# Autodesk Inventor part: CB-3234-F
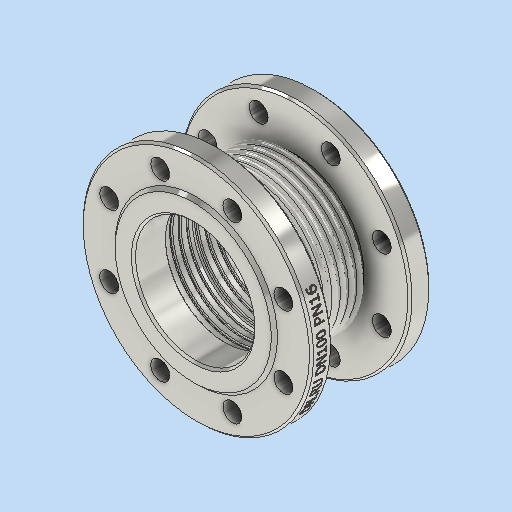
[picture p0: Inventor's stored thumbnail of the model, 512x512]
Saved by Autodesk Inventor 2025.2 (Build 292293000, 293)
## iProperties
Company: DN.RU
Created: 2026-04
Part Number: CB-3234-F
Material: Типовые
Document SubType Name: Modeling
Designer: DN.RU
Density: 6.48472 g/cm^3
Appearance: По умолчанию
Description: D140-02116
Mass: 8200 g
Surface Area: 3641.66 cm^2
Volume: 1264.51 cm^3
Author: DN.RU
Title: Компенсатор сильфонный осевой DN.ru Ду100 Ру16
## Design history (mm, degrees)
sketch "Эскиз1"
  geometry: L1 (0, 0)-(0, -60); L2 (63, -60)-(63, 0); L3 (63, 0)-(0, 0); L4 (63, 0)-(63, -4); L5 (55, -4)-(71, -4); L6 (55, -6.5)-(71, -6.5); L7 (71, -1.5)-(55, -1.5); L8 (71, -4.5)-(55, -4.5); L9 (55, -3.5)-(71, -3.5); L10 (71, -9.5)-(55, -9.5); L11 (55, -11.5)-(71, -11.5); L12 (55, -12)-(71, -12); L13 (55, -14.5)-(71, -14.5); L14 (71, -12.5)-(55, -12.5); L15 (71, -17.5)-(55, -17.5); L16 (55, -19.5)-(71, -19.5); L17 (55, -20)-(71, -20); L18 (55, -22.5)-(71, -22.5); L19 (71, -20.5)-(55, -20.5); L20 (71, -25.5)-(55, -25.5); L21 (55, -27.5)-(71, -27.5); L22 (55, -28)-(71, -28); L23 (55, -30.5)-(71, -30.5); L24 (71, -28.5)-(55, -28.5); L25 (0, -60)-(63, -60); L26 (63, -60)-(57, -60); L27 (63, -25.5)-(61, -25.5); L28 (57, -60)-(57, -28.5); L29 (63, -27.5)-(61, -27.5); L30 (61, -27.5)-(61, -20.5); L31 (63, -19.5)-(61, -19.5); L32 (61, -19.5)-(61, -12.5); L33 (63, -11.5)-(61, -11.5); L34 (61, -11.5)-(61, -4.5); L35 (63, -3.5)-(62, -3.5); L36 (62, -3.5)-(61, 0); L37 (0, -60)-(0, -37); L38 (0, -37)-(110, -37); L39 (110, -37)-(110, -60); L40 (110, -60)-(0, -60); L41 (63, -37)-(63, -47); L42 (63, -47)-(66, -47); L43 (66, -47)-(66, -37); L44 (66, -37)-(63, -37); A1 r 2.5 centre (55, -4) between (55, -1.5) and (55, -6.5); A2 r 2.5 centre (71, -4) between (71, -6.5) and (71, -1.5); A3 r 0.5 centre (55, -4) between (55, -3.5) and (55, -4.5); A4 r 0.5 centre (71, -4) between (71, -4.5) and (71, -3.5); A5 r 0.5 centre (55, -12) between (55, -11.5) and (55, -12.5); A6 r 2.5 centre (55, -12) between (55, -9.5) and (55, -14.5); A7 r 0.5 centre (71, -12) between (71, -12.5) and (71, -11.5); A8 r 2.5 centre (71, -12) between (71, -14.5) and (71, -9.5); A9 r 0.5 centre (55, -20) between (55, -19.5) and (55, -20.5); A10 r 2.5 centre (55, -20) between (55, -17.5) and (55, -22.5); A11 r 0.5 centre (71, -20) between (71, -20.5) and (71, -19.5); A12 r 2.5 centre (71, -20) between (71, -22.5) and (71, -17.5); A13 r 0.5 centre (55, -28) between (55, -27.5) and (55, -28.5); A14 r 2.5 centre (55, -28) between (55, -25.5) and (55, -30.5); A15 r 0.5 centre (71, -28) between (71, -28.5) and (71, -27.5); A16 r 2.5 centre (71, -28) between (71, -30.5) and (71, -25.5); 20 further points
  constraints: 96 end point, 32 point on circle, 19 point on line, 16 centre point, 7 parallel, 7 perpendicular, 6 midpoint, 4 tangent, 2 vertical, 1 horizontal, 69 other
  dimensions: "d0" = 60 distance of L1.start L1.end; "d3" = 4 distance of L2.end L4.end; "d4" = 8 distance of L4.end L5.end; "d5" = 5 diameter of A2; "d6" = 2 distance between parallel lines of L6 L8; "d9" = 8 distance of L4.end point (63, -12); "d15" = 2 distance of L27.start L27.end; "d16" = 2 distance of L29.start L29.end; "d17" = 2 distance of L31.start L31.end; "d18" = 2 distance of L33.start L33.end; "d19" = 1 distance of L35.start L35.end; "d27" = 57 distance between parallel lines of L1 L28; "d28" = 6 distance between parallel lines of L2 L28; "d29" = 23 distance of L1.end L37.end; "d30" = 110 distance of L37.end L38.end; "d31" = 10 distance of L41.start L41.end; "d32" = 3 distance of L42.end L41.end
revolve "Вращение1" sketch "Эскиз1" stored, may be unused: angle "d20" = 360 deg
sketch "Эскиз3" dims "d33" = 180
  geometry: L1 (0, 0)-(71.096, 29.449); L2 (0, 0)-(76.954, 0); C1 r 9 at (83.149, 34.442); C2 r 9 at (34.442, 83.149); C3 r 9 at (-34.442, 83.149); C4 r 9 at (-83.149, 34.442); C5 r 57 at (0, 0) reference; C6 r 77.5 at (0, 0); C7 r 110 at (0, 0) reference; C8 r 9 at (-83.149, -34.442); C9 r 9 at (-34.442, -83.149); C10 r 9 at (34.442, -83.149); C11 r 9 at (83.149, -34.442); 1 further point
  constraints: 9 centre point, 4 end point, 2 coincident, 1 equal length, 1 horizontal, 1 point on line, 20 other
  dimensions: "d34" = 22.5 deg angle of L2 L1; "d35" = 18 diameter of C1; "d38" = 360 deg dimension on point (0, 0) C1.centre (derived); "d40" = 155 diameter of C6
  node "Эскиз — круговой массив1" dims "d38" = 360 deg (derived)
extrude "Выдавливание1" cut sketch "Эскиз3" stored distance "d41" = 10; taper "d42" = 0 deg
extrude "Выдавливание2" cut sketch "Эскиз3" distance "d43" = 3; taper "d44" = 0 deg
chamfer "Фаска2" distance "d45" = 3; stored, may be unused: second distance "d46" = 2, angle "d47" = 45 deg
chamfer "Фаска3" distance "d48" = 2; stored, may be unused: second distance "d49" = 2, angle "d50" = 45 deg
mirror "Зеркальное отражение2"
fillet "Сопряжение2" dims "d51" = 1
node "РабПлоскость2"
sketch "Эскиз4"
  geometry: L1 (-60.476, 3.302)-(81.492, 3.302); L2 (81.492, 3.302)-(81.492, -37.818); L3 (81.492, -37.818)-(-60.476, -37.818); L4 (-60.476, -37.818)-(-60.476, 3.302); 1 further point
  constraints: 2 other
feature "Рельеф2" sketch "Эскиз4" dims "d52" = 0.1, "d53" = 0
node "Твердое тело1"
node "Эскиз — прямоугольный массив1" dims "d9" = 8, "d12" = 10
